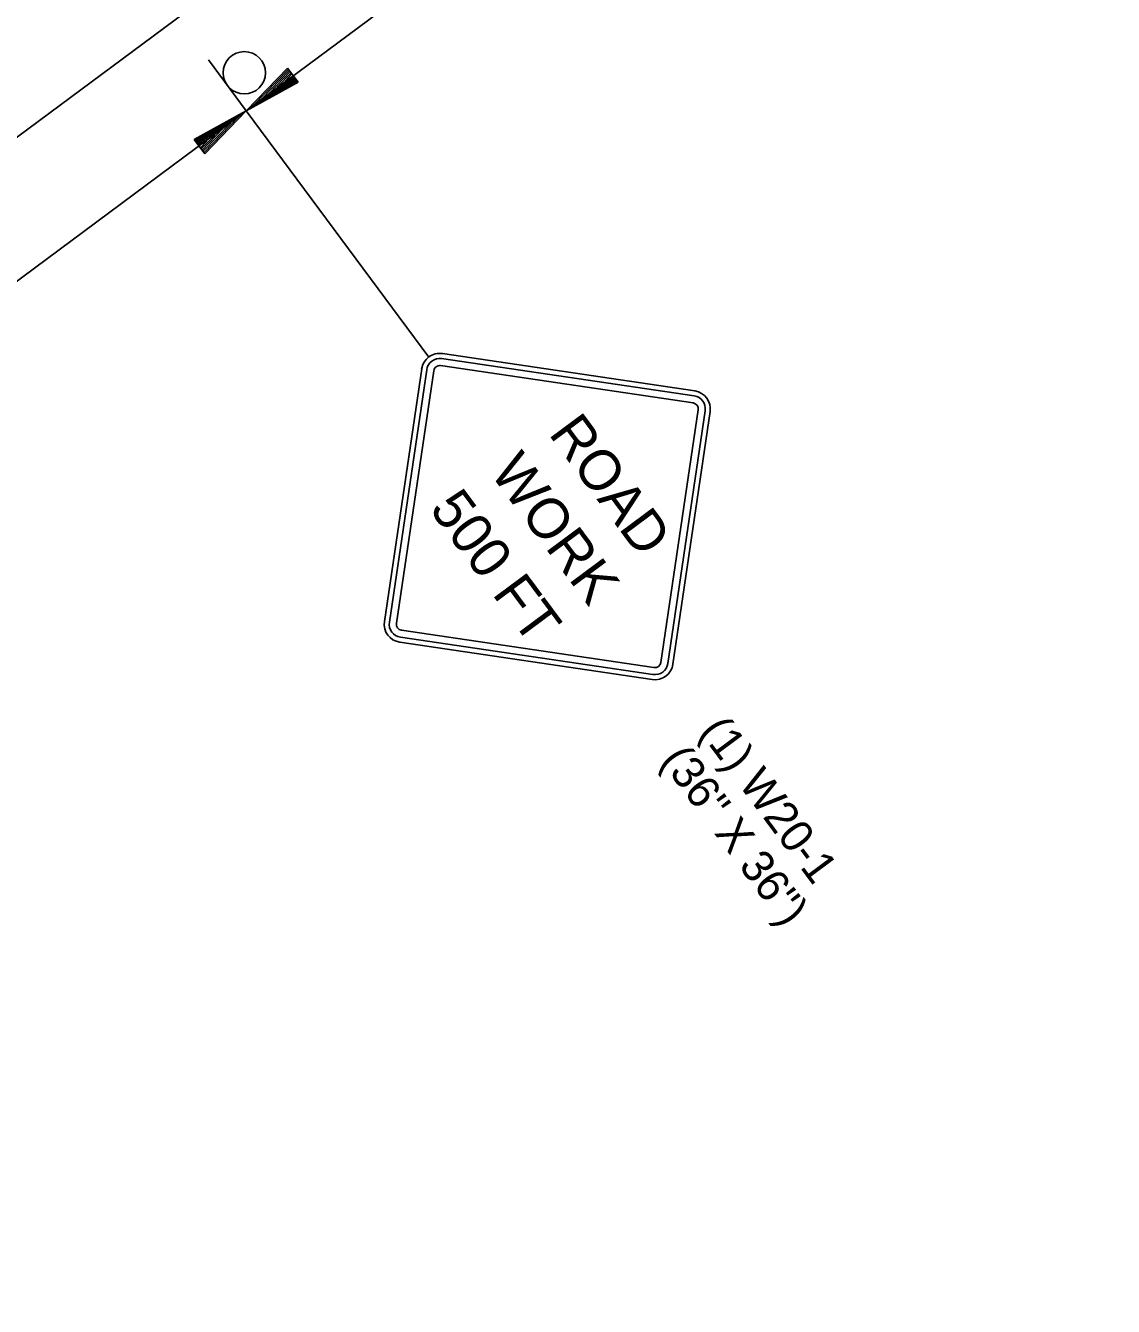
# Model space of a CAD drawing. Extents: x -238 to 1487, y -1123 to 446.
# Drawn here: x 373.5 to 574.9, y -959.1 to -722 of the extents above; entities that cross this region are included whole.
import ezdxf

# ---------------------------------------------------------------- set-up
doc = ezdxf.new("R2010")
doc.units = 0
for name, color, linetype in [('P_TC_Signs_Temporary', 7, 'Continuous'), ('R_Border Prem', 7, 'Continuous'), ('R_Draft', 7, 'Continuous'), ('STAMP', 7, 'Continuous')]:
    doc.layers.add(name, color=color, linetype=linetype)

msp = doc.modelspace()

# ---------------------------------------------------------------- linework, layer by layer
at = {"layer": 'P_TC_Signs_Temporary'}
for p, q in [((450.56, -783.67), (497.3, -790.57)), ((450.69, -782.74), (497.44, -789.64)), ((439.96, -832.33), (446.86, -785.58)), ((440.88, -832.46), (447.79, -785.72)), ((442.18, -832.66), (449.09, -785.91)), ((450.37, -784.96), (497.11, -791.87)), ((498.06, -793.15), (491.15, -839.89)), ((499.35, -793.34), (492.45, -840.08)), ((500.28, -793.48), (493.38, -840.22)), ((489.87, -840.84), (443.13, -833.93)), ((489.54, -843.06), (442.8, -836.16)), ((489.68, -842.14), (442.94, -835.23))]:
    msp.add_line(p, q, dxfattribs=at)
for centre, radius, start, end in [((450.2, -786.08), 3.38, 81.5953, 171.5953), ((450.2, -786.08), 2.44, 81.5953, 171.5953), ((450.2, -786.08), 1.12, 81.5953, 171.5953), ((496.94, -792.98), 2.44, 351.5953, 81.5953), ((496.94, -792.98), 3.37, 351.5953, 81.5953), ((496.94, -792.98), 1.13, 351.5953, 81.5953), ((443.29, -832.82), 3.37, 171.5953, 261.5953), ((443.29, -832.82), 2.44, 171.5953, 261.5953), ((443.29, -832.82), 1.13, 171.5953, 261.5953), ((490.04, -839.73), 3.38, 261.5953, 351.5953), ((490.04, -839.73), 2.44, 261.5953, 351.5953), ((490.04, -839.73), 1.12, 261.5953, 351.5953)]:
    msp.add_arc(centre, radius, start, end, dxfattribs=at)
at = {"layer": 'R_Draft'}
for p, q in [((80.46, -959.1), (552.46, -608.63)), ((574.94, -618.58), (414.36, -737.81)), ((422, -729.89), (414.36, -737.81)), ((422.17, -730.11), (415.8, -736.7)), ((423.98, -732.48), (422, -729.89)), ((423.98, -732.48), (414.36, -737.81)), ((423.82, -732.27), (415.8, -736.7)), ((422.34, -730.33), (417.29, -735.57)), ((423.65, -732.05), (417.29, -735.57)), ((422.5, -730.54), (418.72, -734.46)), ((423.48, -731.83), (418.72, -734.46)), ((422.67, -730.76), (420.19, -733.34)), ((423.31, -731.61), (420.19, -733.34)), ((422.84, -730.98), (421.63, -732.23)), ((423.15, -731.39), (421.63, -732.23)), ((414.36, -737.81), (253.79, -857.04)), ((404.74, -743.14), (414.36, -737.81)), ((404.91, -743.36), (412.92, -738.92)), ((406.56, -745.52), (412.92, -738.92)), ((406.73, -745.74), (414.36, -737.81)), ((414.36, -737.81), (448.19, -783.37)), ((405.07, -743.58), (411.44, -740.06)), ((405.24, -743.8), (410, -741.16)), ((406.23, -745.08), (410, -741.16)), ((406.39, -745.3), (411.44, -740.06)), ((404.74, -743.14), (406.73, -745.74)), ((405.41, -744.02), (408.54, -742.29)), ((405.58, -744.23), (407.1, -743.39)), ((405.89, -744.64), (407.1, -743.39)), ((406.06, -744.86), (408.54, -742.29))]:
    msp.add_line(p, q, dxfattribs=at)
at = {"layer": 'STAMP'}
msp.add_line((414.36, -737.81), (407.36, -728.37), dxfattribs=at)
msp.add_circle((414.01, -730.76), 3.92, dxfattribs=at)

# ---------------------------------------------------------------- texts
at = {"layer": 'P_TC_Signs_Temporary'}
for s, p in [(' ROAD ', (468.56, -795.35)), ('WORK', (459.32, -804.74)), ('500 FT ', (448.13, -811.53))]:
    msp.add_text(s, height=7.5, rotation=306.5953, dxfattribs=at).set_placement(p)
at = {"layer": 'R_Border Prem'}
for s, p in [('(1) W20-1', (498.18, -852.71)), ('(36" X 36")', (490.96, -858.08))]:
    msp.add_text(s, height=6, rotation=306.5953, dxfattribs=at).set_placement(p)

doc.saveas('drawing.dxf')
